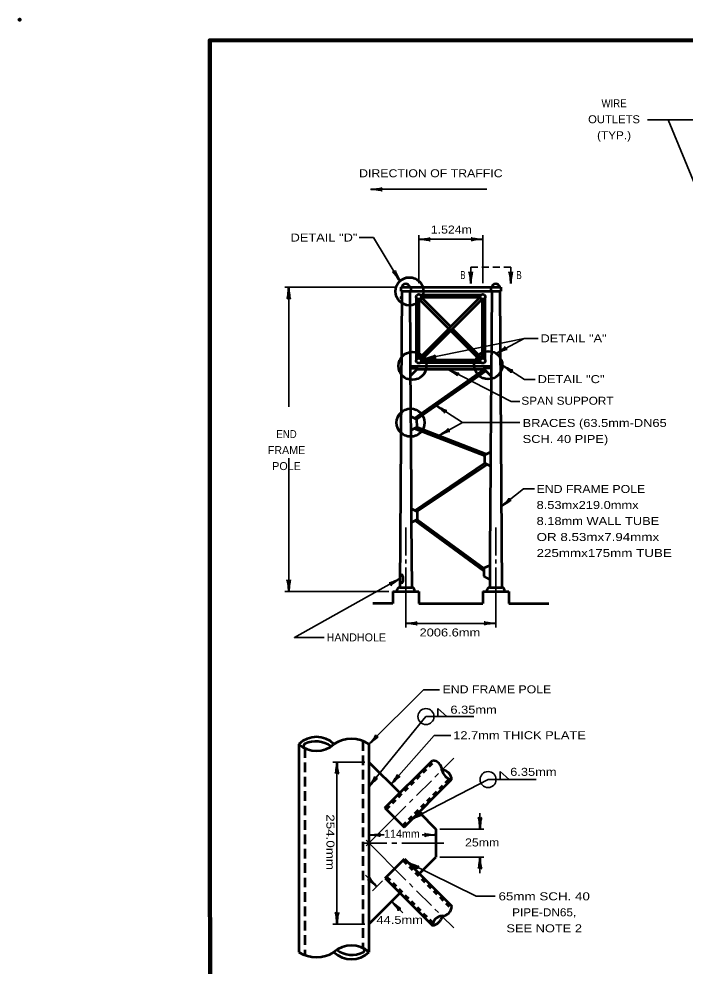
# Model space of a CAD drawing. Extents: x -35 to 821, y -13 to 531.
# Drawn here: x -34.6 to 165.2, y 247.3 to 531.4 of the extents above; entities that cross this region are included whole.
import ezdxf
from ezdxf.enums import TextEntityAlignment as Align

# ---------------------------------------------------------------- set-up
doc = ezdxf.new("R2010")
doc.units = 0
doc.header["$LTSCALE"] = 0.96
doc.header["$PDMODE"] = 32
doc.header["$PDSIZE"] = 0.48
doc.linetypes.add('MEDIUM_DASHED', pattern=[4.5, 3, -1.5])
doc.linetypes.add('SHORT_DASHED', pattern=[2.7, 1.5, -1.2])
doc.layers.add('1', color=7, linetype='Continuous', lineweight=53)

msp = doc.modelspace()

# ---------------------------------------------------------------- linework, layer by layer
at = {"layer": '1', "lineweight": 35}
for p, q in [((160.1576, 501.1801), (153.9972, 501.1801)), ((70.9361, 480.3181), (105.7361, 480.3181)), ((85.3361, 452.1181), (85.3361, 466.5181)), ((104.5361, 452.1181), (104.5361, 466.5181)), ((85.3361, 465.3181), (104.5361, 465.3181)), ((100.9361, 456.9181), (100.9361, 452.1181)), ((103.0361, 456.9181), (100.9361, 456.9181)), ((106.3361, 456.9181), (104.2361, 456.9181)), ((109.6361, 456.9181), (107.5361, 456.9181)), ((112.9361, 456.9181), (110.8361, 456.9181)), ((112.9361, 456.9181), (112.9361, 452.1181)), ((78.7361, 450.9181), (45.1361, 450.9181)), ((46.3361, 450.9181), (46.3361, 415.1129)), ((116.9434, 435.6041), (87.0396, 429.4954)), ((98.4848, 410.3272), (115.712, 410.3272)), ((46.3361, 399.7018), (46.3361, 359.7181)), ((81.4361, 370.5181), (81.4361, 378.9181)), ((108.4361, 370.5181), (108.4361, 378.9181)), ((81.4361, 368.1181), (81.4361, 369.3181)), ((81.4361, 348.9181), (81.4361, 366.9181)), ((108.4361, 368.1181), (108.4361, 369.3181)), ((108.4361, 348.9181), (108.4361, 366.9181)), ((76.3361, 359.7181), (45.1361, 359.7181)), ((81.4361, 350.1181), (108.4361, 350.1181)), ((91.1034, 322.1447), (91.1034, 324.5447)), ((91.1034, 324.5447), (93.8034, 322.1447)), ((70.3974, 301.1387), (87.5034, 322.1447)), ((87.5034, 322.1447), (101.9034, 322.1447)), ((69.1974, 308.4938), (59.5974, 308.4938)), ((60.7974, 308.4938), (60.7974, 259.8941)), ((92.3054, 306.1021), (95.8532, 309.6499)), ((90.184, 303.9807), (91.2447, 305.0414)), ((109.748, 303.2579), (109.748, 305.6579)), ((109.748, 305.6579), (112.448, 303.2579)), ((83.3785, 291.4385), (106.148, 303.2579)), ((84.6685, 298.4652), (89.1234, 302.9201)), ((106.148, 303.2579), (120.548, 303.2579)), ((82.5472, 296.3439), (83.6078, 297.4045)), ((69.5488, 283.3455), (81.4866, 295.2833)), ((103.6974, 288.3941), (103.6974, 293.1941)), ((91.6974, 288.3941), (104.8974, 288.3941)), ((75.7974, 284.1941), (68.5974, 284.1941)), ((69.5488, 285.0426), (81.4868, 273.1047)), ((70.3974, 286.6446), (75.0014, 286.6446)), ((78.7974, 284.1941), (77.2974, 284.1941)), ((92.8974, 284.1941), (80.2974, 284.1941)), ((86.365, 286.6446), (90.4974, 286.6446)), ((91.6974, 279.9941), (104.8974, 279.9941)), ((103.6974, 279.9941), (103.6974, 275.1941)), ((69.3425, 274.5368), (72.7366, 271.1428)), ((71.4638, 269.87), (74.4338, 272.84)), ((82.5474, 272.044), (83.6082, 270.9834)), ((84.6688, 269.9228), (89.1235, 265.4681)), ((77.1916, 266.6883), (80.5857, 263.2942)), ((90.1841, 264.4075), (91.2448, 263.3468)), ((92.3054, 262.2861), (95.8532, 258.7383)), ((69.1974, 259.8941), (59.5974, 259.8941))]:
    msp.add_line(p, q, dxfattribs=at)
at = {"layer": '1'}
for p, q in [((80.236, 449.718), (79.636, 360.9181)), ((79.9361, 450.9181), (79.9361, 449.7181)), ((79.9361, 450.9181), (109.9361, 450.9181)), ((79.9361, 449.7181), (82.9361, 449.7181)), ((82.6361, 449.7181), (82.8893, 412.2183)), ((82.9361, 450.9181), (82.9361, 449.7181)), ((82.9361, 449.7181), (106.9361, 449.7181)), ((107.2361, 449.7181), (107.0638, 424.2181)), ((109.6361, 449.7181), (110.2361, 360.9181)), ((109.9361, 450.9181), (109.9361, 449.7181)), ((84.7061, 429.275), (84.7061, 447.6612)), ((103.8013, 447.9181), (85.4861, 429.6029)), ((85.4861, 429.6029), (85.4861, 447.3333)), ((85.4861, 447.3333), (94.3861, 438.4333)), ((85.743, 448.6981), (104.1292, 448.6981)), ((86.0709, 447.9181), (103.8013, 447.9181)), ((86.0709, 447.9181), (94.9709, 439.0181)), ((86.0709, 429.0181), (104.3861, 447.3333)), ((104.3861, 447.3333), (104.3861, 429.6029)), ((105.1661, 447.6612), (105.1661, 429.275)), ((94.9013, 437.9181), (103.8013, 429.0181)), ((95.4862, 438.503), (104.3861, 429.6029)), ((103.8013, 429.0181), (86.0709, 429.0181)), ((82.7881, 427.2181), (107.0841, 427.2181)), ((82.7921, 426.6181), (85.1922, 426.6181)), ((85.1922, 426.6181), (82.8083, 424.2181)), ((84.0361, 411.6544), (104.9779, 426.3181)), ((84.8942, 426.3181), (104.9779, 426.3181)), ((104.1292, 428.2381), (85.743, 428.2381)), ((104.6799, 426.6181), (107.0638, 424.2181)), ((107.08, 426.6181), (104.6799, 426.6181)), ((84.6952, 411.3304), (105.4381, 425.8548)), ((107.0638, 424.2181), (106.9096, 401.4187)), ((82.8893, 412.2183), (82.9176, 408.0183)), ((82.8893, 412.2183), (84.6952, 411.3304)), ((84.6952, 411.3304), (84.7115, 408.9303)), ((82.9176, 408.0183), (84.7115, 408.9303)), ((82.9176, 408.0183), (83.0765, 384.5224)), ((84.0775, 408.608), (105.1032, 400.4559)), ((84.7107, 409.0525), (105.8029, 400.8746)), ((106.9096, 401.4187), (105.1037, 400.5308)), ((106.9096, 401.4187), (106.8813, 397.2187)), ((84.1419, 383.9986), (105.0874, 398.1307)), ((84.8818, 383.7216), (105.7436, 397.7971)), ((105.1037, 400.5308), (105.0874, 398.1307)), ((106.8813, 397.2187), (105.0874, 398.1307)), ((106.8813, 397.2187), (106.7069, 371.4192)), ((83.0765, 384.5224), (83.1048, 380.3224)), ((83.0765, 384.5224), (84.8824, 383.6345)), ((84.8824, 383.6345), (84.8987, 381.2344)), ((83.1048, 380.3224), (84.8987, 381.2344)), ((84.2832, 380.9215), (104.8695, 365.8709)), ((84.8987, 381.2344), (104.8747, 366.6301)), ((83.1048, 380.3224), (83.2361, 360.9181)), ((106.707, 371.4192), (106.6361, 360.9181)), ((104.8747, 366.6301), (104.8584, 364.23)), ((106.6806, 367.518), (104.8747, 366.6301)), ((106.6806, 367.518), (106.6523, 363.318)), ((80.5482, 364.2181), (80.5482, 362.7181)), ((106.6523, 363.318), (104.8584, 364.23)), ((79.6361, 360.9181), (83.2361, 360.9181)), ((106.6361, 360.9181), (110.2361, 360.9181)), ((77.5361, 359.7181), (85.3361, 359.7181)), ((77.5361, 359.7181), (77.5361, 356.1181)), ((85.3361, 359.7181), (85.3361, 356.1181)), ((104.5361, 359.7181), (112.3361, 359.7181)), ((104.5361, 359.7181), (104.5361, 356.1181)), ((112.3361, 359.7181), (112.3361, 356.1181)), ((77.5361, 356.1181), (71.5361, 356.1181)), ((85.3361, 356.1181), (104.5361, 356.1181)), ((112.3361, 356.1181), (124.3361, 356.1181)), ((49.3974, 313.8941), (49.3974, 251.4941)), ((70.3974, 313.8941), (70.3974, 251.4941)), ((70.3974, 308.4938), (79.6555, 299.2359)), ((75.2006, 294.781), (89.4135, 308.9939)), ((80.9609, 289.0209), (95.1737, 303.2337)), ((75.2006, 294.781), (80.9609, 289.0209)), ((85.4157, 293.4757), (90.4974, 288.3942)), ((90.4974, 288.3941), (90.4974, 279.9941)), ((75.2823, 273.6885), (81.0426, 279.4488)), ((81.0426, 279.4488), (95.2552, 265.2359)), ((85.4973, 274.994), (90.4974, 279.9941)), ((75.2823, 273.6885), (89.4949, 259.4756)), ((70.3974, 259.8941), (79.737, 269.2337))]:
    msp.add_line(p, q, dxfattribs=at)
at = {"layer": '1', "linetype": 'MEDIUM_DASHED'}
for p, q in [((51.1974, 312.6908), (51.1974, 250.5851)), ((68.5974, 314.8031), (68.5974, 252.6974))]:
    msp.add_line(p, q, dxfattribs=at)
at = {"layer": '1', "linetype": 'SHORT_DASHED'}
for p, q in [((75.6248, 294.3567), (90.1483, 308.8802)), ((80.5366, 289.4451), (94.5156, 303.4241)), ((80.6183, 279.0245), (95.1415, 264.501)), ((75.7065, 274.1127), (89.5957, 260.2232))]:
    msp.add_line(p, q, dxfattribs=at)
at = {"layer": '1', "lineweight": 158}
msp.add_lwpolyline([(814.3112, 525.0846), (22.6112, 524.9846), (22.7112, -1.0154)], dxfattribs=at)
at = {"layer": '1', "lineweight": 35}
for points in [[(182.9861, 501.1801), (160.1576, 501.1801), (170.9204, 475.2825), (182.9861, 472.0561)], [(79.674, 452.7713), (71.7566, 465.8649), (67.4684, 465.8649)], [(108.5629, 431.0386), (116.9434, 435.6041), (121.1916, 435.6041)], [(94.1649, 426.3181), (113.0872, 416.7031), (115.712, 416.7031)], [(110.4085, 427.5606), (117.0714, 423.2815), (120.3162, 423.2815)], [(90.593, 415.4601), (98.4848, 410.3272), (91.4237, 406.4497)], [(110.0723, 385.1606), (116.762, 390.4837), (120.0618, 390.4837)], [(79.6494, 363.5307), (48.0269, 345.8295), (56.9137, 345.8295)], [(70.3974, 313.8941), (86.7953, 330.1716), (91.5155, 330.1716)], [(77.0311, 301.8602), (89.9815, 316.4787), (94.9376, 316.4787)], [(82.1066, 278.3848), (102.6079, 268.3173), (108.2721, 268.3173)]]:
    msp.add_lwpolyline(points, dxfattribs=at)
at = {"layer": '1'}
for points in [[(106.9361, 450.9181), (106.9361, 449.7181), (109.9361, 449.7181)], [(80.2239, 447.9181), (79.9239, 447.9181), (79.9239, 447.6181), (80.2239, 447.6181)]]:
    msp.add_lwpolyline(points, dxfattribs=at)
for centre, radius in [((82.5518, 449.7121), 4.2), ((85.3361, 448.0681), 0.75), ((104.5361, 448.0681), 0.75), ((83.4381, 427.3345), 4.2), ((85.3361, 428.8681), 0.75), ((106.2085, 427.5606), 4.2), ((104.5361, 428.8681), 0.75), ((82.8848, 410.3272), 4.2)]:
    msp.add_circle(centre, radius, dxfattribs=at)
at = {"layer": '1', "lineweight": 35}
for centre in [(87.5034, 322.1447), (106.148, 303.2579)]:
    msp.add_circle(centre, 2.4, dxfattribs=at)
at = {"layer": '1'}
for centre, radius, start, end in [((81.4361, 450.7575), 1.2107, 7.62224, 172.37776), ((108.4361, 450.7575), 1.2107, 7.62224, 172.37776), ((80.0982, 364.2181), 0.45, 0, 180), ((79.8154, 359.8461), 1.0869, 99.49518, 186.76502), ((80.0982, 362.7181), 0.45, 180, 0), ((83.0568, 359.8461), 1.0869, 353.23498, 80.50482), ((106.8154, 359.8461), 1.0869, 99.49518, 186.76502), ((110.0568, 359.8461), 1.0869, 353.23498, 80.50482), ((54.6474, 308.5), 7.5272, 45.77548, 134.22453), ((65.1474, 305.735), 9.7022, 57.24064, 122.75936), ((54.6474, 319.7993), 7.9015, 228.36161, 311.63839), ((51.371, 313.3297), 0.662, 110.41349, 254.79699), ((54.4566, 307.0767), 7.6317, 53.28342, 115.75809), ((89.3293, 306.0178), 2.9773, 1.62229, 88.3797), ((92.2212, 303.126), 2.9773, 1.62229, 88.3797), ((95.8396, 306.7678), 3.5963, 190.66794, 259.33007), ((92.2791, 265.3201), 2.9773, 271.62229, 358.3797), ((92.4475, 259.368), 2.9773, 91.6203, 178.37771), ((88.8291, 263.0098), 3.5963, 280.66993, 349.33206), ((65.1474, 245.5889), 7.9015, 48.36161, 131.63839), ((54.6474, 259.6532), 9.7022, 237.24064, 302.75936), ((65.1474, 256.8882), 7.5272, 225.77548, 314.22453), ((65.3382, 258.3115), 7.6317, 233.28342, 295.75809), ((68.4238, 252.0585), 0.662, 290.41349, 74.79699)]:
    msp.add_arc(centre, radius, start, end, dxfattribs=at)
at = {"layer": '1', "lineweight": 40}
for centre, major_axis, ratio, start_param, end_param in [((72.2807, 480.0642), (-2.1077, 0.2108), 0.07063, 3.14071475, 5.41810995), ((72.2807, 480.0642), (-2.1077, 0.2108), 0.07063, 3.14071475, 5.41810995), ((72.2455, 480.6497), (-2.1428, -0.1874), 0.122415, 0.89635335, 3.14159265), ((72.2455, 480.6497), (-2.1428, -0.1874), 0.122415, 0.89635335, 3.14159265), ((86.6807, 465.0642), (-2.1077, 0.2108), 0.07063, 3.14071475, 5.41810995), ((86.6807, 465.0642), (-2.1077, 0.2108), 0.07063, 3.14071475, 5.41810995), ((86.6455, 465.6497), (-2.1428, -0.1874), 0.122415, 0.89635335, 3.14159265), ((86.6455, 465.6497), (-2.1428, -0.1874), 0.122415, 0.89635335, 3.14159265), ((103.2267, 464.9865), (2.1428, 0.1874), 0.122415, 0.89635335, 3.14159265), ((103.1915, 465.572), (2.1077, -0.2108), 0.07063, 3.14071475, 5.41810995), ((78.7127, 453.7203), (1.2691, -1.7367), 0.122415, 0.89635335, 3.14159265), ((79.1955, 454.0533), (0.9103, -1.9127), 0.07063, 3.14071475, 5.41810995), ((100.6045, 453.4275), (0.1874, -2.1428), 0.122415, 0.89635335, 3.14159265), ((100.6045, 453.4275), (0.1874, -2.1428), 0.122415, 0.89635335, 3.14159265), ((101.19, 453.4627), (-0.2108, -2.1077), 0.07063, 3.14071475, 5.41810995), ((101.19, 453.4627), (-0.2108, -2.1077), 0.07063, 3.14071475, 5.41810995), ((112.6045, 453.4275), (0.1874, -2.1428), 0.122415, 0.89635335, 3.14159265), ((113.19, 453.4627), (-0.2108, -2.1077), 0.07063, 3.14071475, 5.41810995), ((46.0822, 449.5735), (0.2108, 2.1077), 0.07063, 3.14071475, 5.41810995), ((46.0822, 449.5735), (0.2108, 2.1077), 0.07063, 3.14071475, 5.41810995), ((46.6677, 449.6087), (-0.1874, 2.1428), 0.122415, 0.89635335, 3.14159265), ((46.6677, 449.6087), (-0.1874, 2.1428), 0.122415, 0.89635335, 3.14159265), ((109.5542, 431.9562), (-1.7921, -1.1897), 0.122415, 0.89635335, 3.14159265), ((109.8651, 431.4589), (1.9517, 0.8232), 0.07063, 6.28230741, 8.55970261), ((88.2562, 430.0823), (-2.062, -0.6125), 0.122415, 0.89635335, 3.14159265), ((88.2562, 430.0823), (-2.062, -0.6125), 0.122415, 0.89635335, 3.14159265), ((88.4078, 429.5157), (-2.1073, -0.2153), 0.07063, 3.14071475, 5.41810995), ((88.4078, 429.5157), (-2.1073, -0.2153), 0.07063, 3.14071475, 5.41810995), ((95.2486, 425.4826), (-1.7836, 1.1427), 0.07063, 3.14071475, 5.41810995), ((95.4825, 426.0205), (-1.9952, 0.8037), 0.122415, 0.89635335, 3.14159265), ((111.4027, 426.6203), (-1.6596, 1.3163), 0.07063, 3.14071475, 5.41810995), ((111.6895, 427.132), (-1.9043, 1.0003), 0.122415, 0.89635335, 3.14159265), ((91.5817, 414.5141), (-1.652, 1.3259), 0.07063, 3.14071475, 5.41810995), ((91.5817, 414.5141), (-1.652, 1.3259), 0.07063, 3.14071475, 5.41810995), ((91.8715, 415.0241), (-1.8985, 1.0113), 0.122415, 0.89635335, 3.14159265), ((91.8715, 415.0241), (-1.8985, 1.0113), 0.122415, 0.89635335, 3.14159265), ((92.4119, 407.3706), (-1.7881, -1.1957), 0.122415, 0.89635335, 3.14159265), ((92.7245, 406.8743), (-1.949, -0.8298), 0.07063, 3.14071475, 5.41810995), ((110.8905, 386.2354), (-1.5601, -1.4809), 0.122415, 0.89635335, 3.14159265), ((111.2826, 385.7991), (-1.7806, -1.1474), 0.07063, 3.14071475, 5.41810995), ((46.0045, 361.0275), (0.1874, -2.1428), 0.122415, 0.89635335, 3.14159265), ((46.59, 361.0627), (-0.2108, -2.1077), 0.07063, 3.14071475, 5.41810995), ((78.3521, 363.0955), (-1.9422, -0.8456), 0.07063, 6.28230741, 8.55970261), ((78.6687, 362.6018), (1.7783, 1.2102), 0.122415, 0.89635335, 3.14159265), ((82.7807, 349.8642), (-2.1077, 0.2108), 0.07063, 3.14071475, 5.41810995), ((82.7807, 349.8642), (-2.1077, 0.2108), 0.07063, 3.14071475, 5.41810995), ((82.7455, 350.4497), (-2.1428, -0.1874), 0.122415, 0.89635335, 3.14159265), ((82.7455, 350.4497), (-2.1428, -0.1874), 0.122415, 0.89635335, 3.14159265), ((107.1267, 349.7865), (2.1428, 0.1874), 0.122415, 0.89635335, 3.14159265), ((107.0915, 350.372), (2.1077, -0.2108), 0.07063, 3.14071475, 5.41810995), ((71.0931, 315.0519), (-1.3888, -1.6426), 0.122415, 0.89635335, 3.14159265), ((71.0931, 315.0519), (-1.3888, -1.6426), 0.122415, 0.89635335, 3.14159265), ((71.5306, 314.6612), (-1.6444, -1.3353), 0.07063, 3.14071475, 5.41810995), ((71.5306, 314.6612), (-1.6444, -1.3353), 0.07063, 3.14071475, 5.41810995), ((60.5435, 307.1492), (0.2108, 2.1077), 0.07063, 3.14071475, 5.41810995), ((61.129, 307.1844), (-0.1874, 2.1428), 0.122415, 0.89635335, 3.14159265), ((70.9672, 302.3634), (-1.2078, -1.7799), 0.122415, 0.89635335, 3.14159265), ((70.9672, 302.3634), (-1.2078, -1.7799), 0.122415, 0.89635335, 3.14159265), ((77.6512, 303.0602), (-1.2807, -1.7282), 0.122415, 0.89635335, 3.14159265), ((77.6512, 303.0602), (-1.2807, -1.7282), 0.122415, 0.89635335, 3.14159265), ((78.1128, 302.6983), (-1.5554, -1.4379), 0.07063, 3.14071475, 5.41810995), ((78.1128, 302.6983), (-1.5554, -1.4379), 0.07063, 3.14071475, 5.41810995), ((71.4433, 302.021), (1.4944, 1.5013), 0.07063, 6.28230741, 8.55970261), ((71.4433, 302.021), (1.4944, 1.5013), 0.07063, 6.28230741, 8.55970261), ((84.3879, 292.3361), (-1.8155, -1.1536), 0.122415, 0.89635335, 3.14159265), ((84.3879, 292.3361), (-1.8155, -1.1536), 0.122415, 0.89635335, 3.14159265), ((84.6889, 291.8326), (-1.9678, -0.784), 0.07063, 3.14071475, 5.41810995), ((84.6889, 291.8326), (-1.9678, -0.784), 0.07063, 3.14071475, 5.41810995), ((103.3658, 289.7035), (0.1874, -2.1428), 0.122415, 0.89635335, 3.14159265), ((103.9513, 289.7387), (-0.2108, -2.1077), 0.07063, 3.14071475, 5.41810995), ((71.7068, 286.9762), (-2.1428, -0.1874), 0.122415, 0.89635335, 3.14159265), ((89.1528, 286.8985), (2.1077, -0.2108), 0.07063, 3.14071475, 5.41810995), ((71.742, 286.3907), (-2.1077, 0.2108), 0.07063, 3.14071475, 5.41810995), ((89.188, 286.313), (2.1428, 0.1874), 0.122415, 0.89635335, 3.14159265), ((103.4435, 278.6495), (0.2108, 2.1077), 0.07063, 3.14071475, 5.41810995), ((104.029, 278.6847), (-0.1874, 2.1428), 0.122415, 0.89635335, 3.14159265), ((83.2016, 277.5642), (-1.799, 1.1183), 0.07063, 3.14071475, 5.41810995), ((83.4281, 278.1052), (-2.006, 0.7763), 0.122415, 0.89635335, 3.14159265), ((71.5762, 271.8342), (1.6477, -1.3827), 0.122415, 0.89635335, 3.14159265), ((71.9654, 272.2731), (-1.3414, 1.6394), 0.07063, 6.28230741, 8.55970261), ((77.9628, 265.558), (1.3414, -1.6394), 0.07063, 6.28230741, 8.55970261), ((78.352, 265.9968), (-1.6477, 1.3827), 0.122415, 0.89635335, 3.14159265), ((60.4658, 261.2035), (0.1874, -2.1428), 0.122415, 0.89635335, 3.14159265), ((61.0513, 261.2387), (-0.2108, -2.1077), 0.07063, 3.14071475, 5.41810995)]:
    msp.add_ellipse(centre, major_axis=major_axis, ratio=ratio, start_param=start_param, end_param=end_param, dxfattribs=at)
at = {"layer": '1'}
msp.add_point((-34.3888, 531.1846), dxfattribs=at)

# ---------------------------------------------------------------- texts
for s, width, p in [('WIRE', 0.9, (143.9369, 504.9314)), ('OUTLETS', 1.05, (143.9369, 500.1314)), ('(TYP.)', 1.1, (143.9369, 495.3314)), ('END', 0.9, (45.6596, 405.692)), ('65mm SCH. 40', 1.25, (122.9773, 267.034)), ('PIPE-DN65,', 1.1, (122.9773, 262.234)), ('SEE NOTE 2', 1.2, (122.9773, 257.434))]:
    msp.add_text(s, height=2.4, dxfattribs=dict(at, width=width)).set_placement(p, align=Align.CENTER)
for s, width, p in [('DIRECTION OF TRAFFIC', 1.15, (67.4488, 483.9296)), ('1.524m', 1.15, (88.9637, 467.0427)), ('DETAIL "D"', 1.2, (46.8688, 464.6485)), ('B', 0.75, (97.7666, 453.4012)), ('B', 0.75, (114.6321, 453.4012)), ('DETAIL "A"', 1.2, (121.8601, 434.4213)), ('DETAIL "C"', 1.2, (121.0028, 422.1717)), ('SPAN SUPPORT', 1.1, (116.1269, 415.6938)), ('BRACES (63.5mm-DN65', 1.2, (116.5078, 409.026)), ('SCH. 40 PIPE)', 1.2, (116.5078, 404.226)), ('END FRAME POLE', 1.15, (120.6904, 389.2216)), ('8.53mx219.0mmx', 1.2, (120.6904, 384.4216)), ('8.18mm WALL TUBE', 1.2, (120.6904, 379.6216)), ('OR 8.53mx7.94mmx', 1.25, (120.6904, 374.8216)), ('225mmx175mm TUBE', 1.25, (120.6904, 370.0216)), ('2006.6mm', 1.2, (85.5779, 346.184)), ('END FRAME POLE', 1.15, (92.4931, 329.1253)), ('6.35mm', 1.2, (94.8385, 323.0186)), ('12.7mm THICK PLATE', 1.2, (95.6772, 315.3562)), ('6.35mm', 1.2, (112.7716, 304.3707)), ('25mm', 1.15, (99.238, 283.1901)), ('44.5mm', 1.2, (72.6609, 259.9759))]:
    msp.add_text(s, height=2.4, dxfattribs=dict(at, width=width)).set_placement(p)
for s, p in [('FRAME', (45.6596, 400.892)), ('POLE', (45.6594, 396.092))]:
    msp.add_text(s, height=2.4, dxfattribs=at).set_placement(p, align=Align.CENTER)
for s, p in [('HANDHOLE', (57.6999, 344.7048)), ('114mm', (74.9355, 285.8104))]:
    msp.add_text(s, height=2.4, dxfattribs=at).set_placement(p)
at = {"layer": '1', "width": 1.25}
msp.add_text('254.0mm', height=2.4, rotation=270, dxfattribs=at).set_placement((57.6395, 292.8411))

doc.saveas('drawing.dxf')
